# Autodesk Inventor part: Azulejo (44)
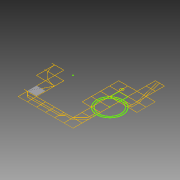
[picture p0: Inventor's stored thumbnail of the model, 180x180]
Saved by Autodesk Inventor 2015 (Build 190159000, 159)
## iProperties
Created: 2015-04
Part Number: Azulejo (44)
Material: Genérico
Document SubType Name: Modeling
Designer: Felipe
Density: 1 g/cm^3
Appearance: Padrão
Author: Felipe
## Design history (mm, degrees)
sketch "Sketch1"
  geometry: L1 (-1510, -7490)-(-1510, -6010); L2 (-3010, -1490)-(-3010, -10); L3 (-2990, 10)-(-1510, 10); L4 (-1510, -10)-(-2990, -10); L5 (-1510, -1490)-(-1510, -10); L6 (-1490, -10)-(-1490, -1490); L7 (-1490, -1490)-(-10, -1490); L8 (-10, -1510)-(-1490, -1510); L9 (-10, -2990)-(-10, -1510); L10 (-10, -5990)-(-10, -4510); L11 (-1490, -7490)-(-10, -7490); L12 (4490, -6010)-(3010, -6010); L13 (10, -1510)-(10, -2990); L14 (10, -3010)-(10, -4490); L15 (10, -4510)-(10, -5990); L16 (10, -5990)-(1490, -5990); L17 (1490, -6010)-(10, -6010); L18 (10, -7490)-(1490, -7490); L19 (1510, -5990)-(2990, -5990); L20 (2990, -6010)-(1510, -6010); L21 (1510, -7490)-(2990, -7490); L22 (4490, 1510)-(4490, 2990); L23 (4490, 10)-(4490, 1490); L24 (4490, -1490)-(4490, -10); L25 (4490, -2990)-(4490, -1510); L26 (3010, -5990)-(4490, -5990); L27 (3010, -7490)-(4490, -7490); L28 (4510, 3010)-(5990, 3010); L29 (5990, 2990)-(4510, 2990); L30 (4510, 2990)-(4510, 1510); L31 (4510, 1510)-(5990, 1510); L32 (5990, 1510)-(5990, 1740.185); L33 (5990, 1760.2)-(5990, 2259.8); L34 (5990, 2279.815)-(5990, 2990); L35 (5990, 1490)-(4510, 1490); L36 (4510, 1490)-(4510, 10); L37 (4510, 10)-(5990, 10); L38 (5990, 10)-(5990, 1490); L39 (5975.983, -10)-(4510, -10); L40 (4510, -10)-(4510, -1490); L41 (5990, -1510)-(5782.897, -1510); L42 (5782.897, -1510)-(5688.66, -1510); L43 (5668.66, -1510)-(5482.895, -1510); L44 (5482.895, -1510)-(5388.656, -1510); L45 (5368.656, -1510)-(4510, -1510); L46 (4510, -1510)-(4510, -2990); L47 (4510, -2990)-(5975.983, -2990); L48 (5990, -2975.728)-(5990, -2837.377); L49 (5990, -2837.377)-(5990, -2536.247); L50 (5990, -2500.476)-(5990, -2317.632); L51 (5990, -2317.632)-(5990, -1510); L52 (5990, -3010)-(4510, -3010); L53 (5990, -4490)-(5990, -3010); L54 (4510, -5990)-(5990, -5990); L55 (5990, -5990)-(5990, -4510); L56 (4510, -7490)-(5990, -7490); L57 (5990, -7490)-(5990, -6310); L58 (5990, -6290)-(5990, -6010); L59 (7490, 4510)-(7490, 5990); L60 (6010, 3010)-(7490, 3010); L61 (7490, 3010)-(7490, 4490); L62 (7490, 2990)-(6010, 2990); L63 (6010, 2990)-(6010, 2279.815); L64 (6010, 2259.8)-(6010, 1760.2)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; A1 r 250 centre (6000, 2010) between (5990, 2259.8) and (5990, 1760.2); A2 r 250 centre (6000, 2010) between (6010, 1760.2) and (6010, 2259.8); A3 r 270 centre (6000, 2010) between (5990, 2279.815) and (5990, 1740.185); A4 r 270 centre (6000, 2010) between (6010, 1740.185) and (6010, 2279.815); A5 r 3010.017 centre (0, 0) between (-1490, -2615.358) and (-346.554, -2990); A6 r 2990.017 centre (0, 0) between (-1490, -2592.316) and (-10, -2990); A7 r 3010.017 centre (0, 0) between (-2603.863, -1510) and (-1510, -2603.863); A8 r 2990.017 centre (0, 0) between (-2580.717, -1510) and (-1510, -2580.717); A9 r 3010.017 centre (0, 0) between (-2990, -346.554) and (-2615.358, -1490); A10 r 2990.017 centre (0, 0) between (-2990, -10) and (-2592.316, -1490); A11 r 2131.367 centre (7500, -1500) between (7490, 631.344) and (6010, 24.017); A12 r 2131.367 centre (7500, -1500) between (5975.983, -10) and (5368.656, -1490); A13 r 2131.367 centre (7500, -1500) between (5368.656, -1510) and (5975.983, -2990); A14 r 2131.367 centre (7500, -1500) between (6010, -3024.017) and (7190, -3608.703); A15 r 1831.367 centre (7500, -1500) between (7490.321, 331.342) and (6463.753, 10); A16 r 1831.367 centre (7500, -1500) between (7489.976, 331.34) and (6010, -435.196); A17 r 1831.367 centre (7500, -1500) between (5990, -463.753) and (5668.66, -1490); A18 r 1831.367 centre (7500, -1500) between (5668.66, -1510) and (5990, -2536.247); A19 r 1831.367 centre (7500, -1500) between (6010, -2564.804) and (6435.196, -2990); A20 r 1831.367 centre (7500, -1500) between (6463.753, -3010) and (7490, -3331.34); A21 r 2111.367 centre (7500, -1500) between (7490.389, 611.346) and (6024.272, 10); A22 r 2111.367 centre (7500, -1500) between (5990, -24.272) and (5388.656, -1490); A23 r 2111.367 centre (7500, -1500) between (5388.656, -1510) and (5990, -2975.728); A24 r 2111.367 centre (7500, -1500) between (6024.272, -3010) and (7210, -3591.357); A25 r 1811.367 centre (7499.986, -1499.91) between (7490.524, 311.432) and (6499.51, 10.09); A26 r 1811.367 centre (7500, -1500) between (6469.975, -10) and (6010, -469.975); A27 r 1811.367 centre (7500, -1500) between (5990, -499.524) and (5688.66, -1490); A28 r 1811.367 centre (7500, -1500) between (5688.66, -1510) and (5990, -2500.476); A29 r 1811.367 centre (7500, -1500) between (6010, -2530.025) and (6469.975, -2990); A30 r 1811.367 centre (7500, -1500) between (6499.524, -3010) and (7490, -3311.34); A31 r 449.871 centre (7499.449, -4060.672) between (7510, -4510.419) and (7521.546, -4510); A32 r 2111.367 centre (7500, -1500) between (7490.019, 611.344) and (7490.389, 611.346); A33 r 1831.367 centre (7500, -1500) between (7489.976, 331.34) and (7490.321, 331.342); A34 r 1811.367 centre (7499.986, -1499.91) between (7489.986, 311.429) and (7490.524, 311.432); A35 r 2131.367 centre (7500, -1500) between (7510, -3631.344) and (7190, -3608.703); A36 r 2131.367 centre (7500, -1500) between (7210, -3611.546) and (7490, -3631.344); 12 further points
  constraints: 718 end point, 82 point on circle, 36 centre point, 14 point on line, 3 concentric, 2 parallel, 2 perpendicular, 1 collinear, 1 horizontal, 1 vertical, 1 other
extrude "Extrusion1" new body sketch "Sketch1" distance "d0" = 60; taper "d1" = 0 deg
extrude "Extrusion2" new body sketch "Sketch1" distance "d2" = 60; taper "d3" = 0 deg
body "Solid1"
body "Solid2"
